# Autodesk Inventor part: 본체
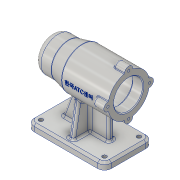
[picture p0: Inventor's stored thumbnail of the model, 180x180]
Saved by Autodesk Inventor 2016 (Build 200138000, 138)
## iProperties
Created: 2019-07
Part Number: 본체
Material: 알루미늄 6061
Document SubType Name: Modeling
Designer: 3sil_cad003
Density: 2.7 g/cm^3
Appearance: 알루미늄 - 평지
Mass: 644.388 g
Surface Area: 654.094 cm^2
Volume: 238.662 cm^3
Author: 3sil_cad003
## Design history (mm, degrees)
sketch "스케치1"
  geometry: L1 (-56, 35)-(56, 35); L2 (56, 35)-(56, -35); L3 (56, -35)-(-56, -35); L4 (-56, -35)-(-56, 35); L5 (-56, 35)-(56, -35); L6 (56, 35)-(-56, -35); 1 further point
  constraints: 12 end point, 2 midpoint, 2 parallel, 1 horizontal, 1 perpendicular
  dimensions: "d0" = 112 distance of L2.end L3.end; "d1" = 70 distance of L3.end L1.start
extrude "돌출1" new body sketch "스케치1" distance "d2" = 10; taper "d3" = 0 deg
sketch "스케치2"
  geometry: L1 (-56, 0)-(56, 0) reference; L2 (-56, 80)-(56, 80); L3 (-56, 80)-(-56, 105); L4 (-56, 105)-(-31, 105); L5 (-31, 105)-(-11, 110); L6 (-11, 110)-(56, 110); L7 (56, 110)-(56, 80); L8 (-50, 80)-(-50, 90.5); L9 (-50, 90.5)-(-47, 90.5); L10 (-47, 90.5)-(-47, 96); L11 (-47, 96)-(-43, 96); L12 (-43, 96)-(-43, 97.5); L13 (-43, 97.5)-(-25, 97.5); L14 (-25, 97.5)-(-25, 101); L15 (-25, 101)-(-13, 101); L16 (-13, 101)-(-13, 104); L17 (-13, 104)-(41, 104); L18 (41, 104)-(41, 101); L19 (41, 101)-(56, 101); 1 further point
  constraints: 36 end point, 14 perpendicular, 2 point on line, 1 horizontal, 1 parallel, 1 vertical
  dimensions: "d6" = 112 distance of L2.start L2.end; "d7" = 80 distance from line of L2 point (0, 0); "d8" = 56 horizontal distance of point (0, 0) L2.start (= 0.5 x d6); "d9" = 50 diameter of L4 L2; "d10" = 60 diameter of L6 L2; "d11" = 25 distance of L3.end L4.end; "d12" = 45 distance from line of L5.end L3; "d13" = 21 diameter of L9 L2; "d14" = 3 distance of L8.end L9.end; "d15" = 32 diameter of L11 L2; "d16" = 4 distance of L10.end L11.end; "d17" = 18 distance of L12.end L13.end; "d18" = 12 distance of L14.end L15.end; "d19" = 35 diameter of L13 L2; "d20" = 42 diameter of L15 L2; "d21" = 48 diameter of L17 L2; "d22" = 54 distance between parallel lines of L18 L16; "d23" = 15 distance of L18.end L19.end; "d24" = 42 diameter of L19 L2
revolve "회전1" sketch "스케치2" stored, may be unused: angle "d25" = 90 deg
sketch "스케치3"
  geometry: C1 r 30 at (0, 0) reference; C2 r 30 at (0, 0) reference; C3 r 30 at (0, 0) reference; C4 r 21 at (0, 0) reference; C5 r 6 at (0, 30); 1 further point
  constraints: 1 centre point
  dimensions: "d27" = 30 distance of C1.centre C5.centre; "d28" = 12 diameter of C5
extrude "돌출2" join sketch "스케치3" distance "d29" = 16; taper "d30" = 0 deg
sketch "스케치4"
  geometry: A1 r 6 centre (0, 0) between (5.97, -0.6) and (-5.97, -0.6) reference; 2 further points
  constraints: 1 coincident
hole "구멍1" sketch "스케치4" at (0, 0) diameter "d31" = 3.242; stored, may be unused: countersink angle "d35" = 90 deg, drill point angle "d37" = 118 deg; dims "d32" = 8, "d33" = 4, "d34" = 2, "d36" = 11
sketch "스케치5"
  geometry: L1 (56, 10)-(-56, 10) reference; L2 (-36, 10)-(-28.334, 31.063); 1 further point
  constraints: 2 end point, 1 point on line
  dimensions: "d41" = 110 deg angle of L1 L2; "d42" = 20 distance of L2.start L1.end
feature "리브1" sketch "스케치5" dims "d43" = 40, "d44" = 8, "d45" = 0, "d46" = 0, "d47" = 1, "d48" = 1
sketch "스케치6"
  geometry: L1 (56, -35)-(56, 35) reference; L2 (0, 4)-(31, 4); L3 (31, 4)-(31, -4); L4 (31, -4)-(0, -4); L5 (0, -4)-(0, 4); 1 further point
  constraints: 8 end point, 2 parallel, 1 horizontal, 1 perpendicular
  dimensions: "d50" = 25 distance between parallel lines of L1 L3; "d51" = 0 distance from line of point (0, 0) L5; "d52" = 8 distance of L2.end L3.end; "d53" = 4 distance of L4.end point (0, 0)
extrude "돌출3" join sketch "스케치6" stored distance "d54" = 16; taper "d55" = 0 deg
sketch "스케치7"
  geometry: L1 (10, -35)-(10, 35) reference; L2 (10, 28)-(34.996, 23.592); 1 further point
  constraints: 2 end point, 1 point on line
  dimensions: "d56" = 100 deg angle of L1 L2; "d57" = 7 distance of L2.start L1.end
feature "리브2" sketch "스케치7" dims "d58" = 40, "d59" = 8, "d60" = 0, "d61" = 0, "d62" = 1, "d63" = 1
fillet "모깎기1" dims "d64" = 10
sketch "스케치10"
  geometry: A1 r 10 centre (-46, 25) between (-46, 35) and (-56, 25) reference; A2 r 10 centre (-46, -25) between (-56, -25) and (-46, -35) reference; A3 r 10 centre (46, -25) between (46, -35) and (56, -25) reference; A4 r 10 centre (46, 25) between (56, 25) and (46, 35) reference; 1 further point
hole "구멍2" sketch "스케치10" at (-46, 25), (-46, -25), (46, 25), (46, -25) diameter "d65" = 6; stored, may be unused: countersink angle "d69" = 90 deg, drill point angle "d71" = 118 deg; dims "d66" = 8, "d67" = 4, "d68" = 2, "d70" = 11
fillet "모깎기3" dims "d73" = 10
fillet "모깎기4" dims "d74" = 3
fillet "모깎기6" dims "d76" = 3
fillet "모깎기7" dims "d77" = 1
fillet "모깎기8" dims "d78" = 3
fillet "모깎기9" dims "d79" = 3
fillet "모깎기10" dims "d80" = 3
fillet "모깎기11" dims "d81" = 0.3
chamfer "모따기1" distance "d82" = 1; stored, may be unused: second distance "d83" = 1, angle "d84" = 45 deg
chamfer "모따기2" distance "d85" = 3; stored, may be unused: second distance "d86" = 1, angle "d87" = 45 deg
fillet "모깎기12" dims "d88" = 3
fillet "모깎기13" dims "d89" = 3
fillet "모깎기14" dims "d90" = 3
node "작업 평면1"
sketch "스케치11"
  geometry: L1 (56, 86.771)-(56, 109.226) reference; L2 (46, 0)-(-46, 0) reference; 2 further points
  constraints: 1 other
  dimensions: "d92" = 42 distance from line of L1 point (14, 80); "d93" = 80 distance from line of L2 point (14, 80)
feature "엠보싱1" sketch "스케치11" dims "d0" = 112, "d1" = 70, "d94" = 0.5, "d95" = 0
node "솔리드1"
pattern_circular "원형 패턴1" dims angle "d39" = 360 deg
mirror "대칭1"
node "투영된 루프1"
